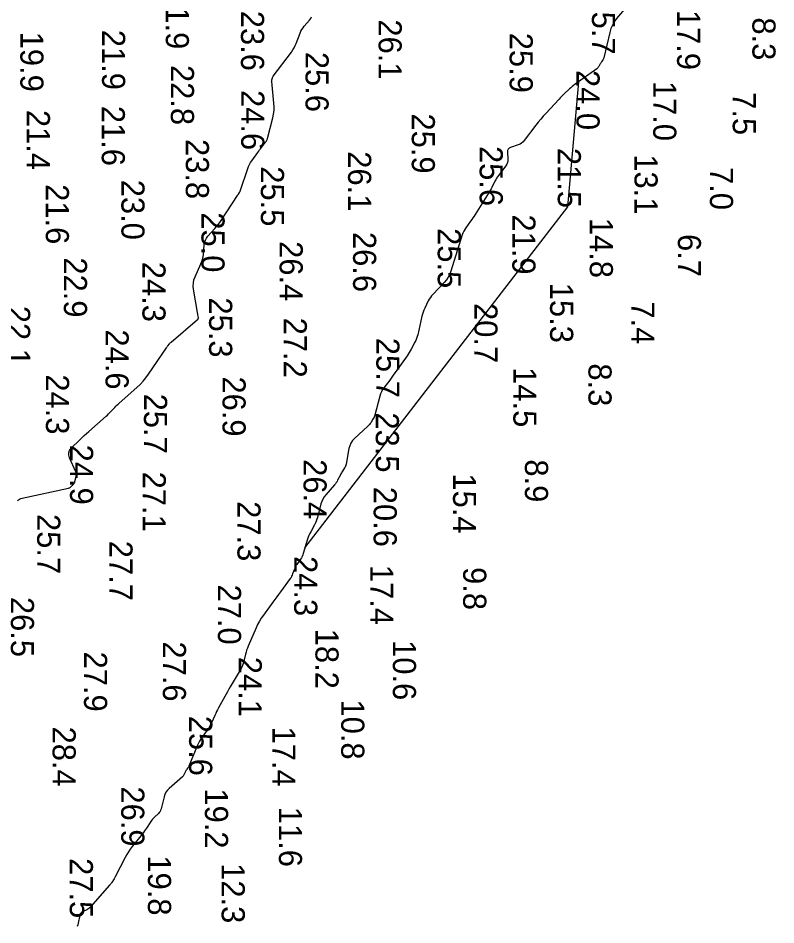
# Model space of a CAD drawing. Extents: x 1178573 to 1187098, y 693282 to 751751.
# Drawn here: x 1181936.7 to 1182346.5, y 721748.7 to 722239.3 of the extents above; entities that cross this region are included whole.
import ezdxf

# ---------------------------------------------------------------- set-up
doc = ezdxf.new("R2010")
doc.units = 0
for name, color, linetype in [('G-ANNO-PATT', 7, 'Continuous'), ('V-HYDS-MAJR', 7, 'Continuous'), ('V-HYDS-SOUN', 7, 'Continuous')]:
    doc.layers.add(name, color=color, linetype=linetype)

msp = doc.modelspace()

# ---------------------------------------------------------------- linework, layer by layer
at = {"layer": 'G-ANNO-PATT'}
for p, q in [((1182234, 722137.21), (1182239.89, 722204.89)), ((1182091.82, 721952.67), (1182234, 722137.21))]:
    msp.add_line(p, q, dxfattribs=at)
for points in [[(1181936.3, 721978.32), (1181936.88, 721978.75), (1181937.49, 721979.11), (1181938.14, 721979.38), (1181938.83, 721979.58), (1181964, 721985.05), (1181964.28, 721985.13), (1181964.55, 721985.24), (1181964.8, 721985.39), (1181965.03, 721985.57), (1181966.15, 721986.59), (1181966.25, 721986.69), (1181966.35, 721986.79), (1181966.44, 721986.89), (1181966.52, 721987), (1181966.86, 721987.44), (1181966.94, 721987.56), (1181967, 721987.68), (1181967.06, 721987.8), (1181967.1, 721987.93), (1181968.05, 721991.37), (1181968.16, 721991.98), (1181968.17, 721992.59), (1181968.07, 721993.19), (1181967.86, 721993.77), (1181964.47, 722001.36), (1181964.04, 722002.78), (1181964.05, 722004.12), (1181964.52, 722005.37), (1181965.43, 722006.54), (1181970.11, 722011.17), (1181971.27, 722012.31), (1181972.45, 722013.43), (1181973.65, 722014.54), (1181974.87, 722015.62), (1181984.36, 722024), (1181984.97, 722024.56), (1181985.57, 722025.12), (1181986.16, 722025.7), (1181986.74, 722026.3), (1181989.01, 722028.69), (1181989.58, 722029.29), (1181990.17, 722029.87), (1181990.77, 722030.44), (1181991.38, 722030.99), (1182000.93, 722039.48), (1182002.68, 722041.12), (1182004.31, 722042.87), (1182005.82, 722044.71), (1182007.23, 722046.65), (1182016.89, 722060.93), (1182017.09, 722061.21), (1182017.29, 722061.48), (1182017.49, 722061.75), (1182017.71, 722062.02), (1182018.57, 722063.08), (1182018.79, 722063.34), (1182019.02, 722063.59), (1182019.26, 722063.83), (1182019.52, 722064.06), (1182033.79, 722076.17), (1182034.02, 722076.41), (1182034.16, 722076.69), (1182034.22, 722076.99), (1182034.2, 722077.32), (1182033.96, 722078.7), (1182033.89, 722079.04), (1182033.83, 722079.39), (1182033.77, 722079.73), (1182033.71, 722080.08), (1182031.57, 722092.62), (1182031.4, 722094.33), (1182031.48, 722096), (1182031.81, 722097.65), (1182032.4, 722099.26), (1182035.59, 722106.43), (1182036.08, 722107.64), (1182036.45, 722108.88), (1182036.73, 722110.16), (1182036.89, 722111.45), (1182037.35, 722116.7), (1182037.56, 722117.97), (1182037.96, 722119.15), (1182038.56, 722120.26), (1182039.34, 722121.28), (1182043.14, 722125.48), (1182044.05, 722126.52), (1182044.91, 722127.6), (1182045.73, 722128.71), (1182046.51, 722129.85), (1182055.29, 722143.26), (1182055.42, 722143.47), (1182055.56, 722143.67), (1182055.69, 722143.87), (1182055.83, 722144.07), (1182056.38, 722144.87), (1182056.51, 722145.08), (1182056.63, 722145.29), (1182056.73, 722145.51), (1182056.82, 722145.73), (1182060.93, 722157.92), (1182061.35, 722159.04), (1182061.85, 722160.11), (1182062.43, 722161.15), (1182063.09, 722162.14), (1182066.32, 722166.64), (1182066.8, 722167.31), (1182067.29, 722167.98), (1182067.79, 722168.64), (1182068.29, 722169.3), (1182070.31, 722171.92), (1182070.77, 722172.59), (1182071.17, 722173.3), (1182071.49, 722174.05), (1182071.73, 722174.83), (1182074.46, 722185.27), (1182074.89, 722187.25), (1182075.13, 722189.25), (1182075.19, 722191.26), (1182075.07, 722193.29), (1182073.85, 722204.97), (1182073.83, 722205.23), (1182073.84, 722205.48), (1182073.88, 722205.74), (1182073.95, 722205.98), (1182074.26, 722206.97), (1182074.35, 722207.22), (1182074.45, 722207.45), (1182074.58, 722207.67), (1182074.73, 722207.88), (1182084.52, 722220.94), (1182085.29, 722222.05), (1182085.98, 722223.2), (1182086.59, 722224.4), (1182087.12, 722225.64), (1182089.24, 722231.2), (1182089.68, 722232.19), (1182090.19, 722233.14), (1182090.79, 722234.03), (1182091.48, 722234.88), (1182094.38, 722238.15), (1182095.01, 722239.01), (1182095.46, 722239.93)], [(1182239.89, 722204.89), (1182237.91, 722203.49), (1182237.12, 722202.9), (1182236.35, 722202.29), (1182235.6, 722201.65), (1182234.88, 722200.98), (1182232.03, 722198.26), (1182231.33, 722197.57), (1182230.63, 722196.87), (1182229.94, 722196.17), (1182229.27, 722195.45), (1182222.1, 722187.71), (1182220.7, 722186.16), (1182219.35, 722184.59), (1182218.03, 722182.98), (1182216.76, 722181.34), (1182210.49, 722173.07), (1182209.81, 722172.3), (1182209.04, 722171.65), (1182208.18, 722171.12), (1182207.23, 722170.73), (1182203.1, 722169.33), (1182202.3, 722168.94), (1182201.75, 722168.38), (1182201.44, 722167.66), (1182201.36, 722166.78), (1182201.55, 722162.93), (1182201.52, 722161.99), (1182201.33, 722161.1), (1182200.99, 722160.25), (1182200.49, 722159.46), (1182196.52, 722154.15), (1182195.98, 722153.4), (1182195.48, 722152.62), (1182195.01, 722151.83), (1182194.57, 722151.02), (1182192.89, 722147.72)], [(1182192.89, 722147.72), (1182192.47, 722146.9), (1182192.02, 722146.09), (1182191.56, 722145.3), (1182191.08, 722144.51), (1182183.9, 722133.05), (1182183.31, 722132.12), (1182182.7, 722131.21), (1182182.08, 722130.31), (1182181.44, 722129.41), (1182178.85, 722125.87), (1182178.24, 722124.97), (1182177.71, 722124.02), (1182177.26, 722123.03), (1182176.9, 722122), (1182170.78, 722102.41), (1182170.15, 722100.71), (1182169.33, 722099.12), (1182168.33, 722097.64), (1182167.16, 722096.26), (1182161.1, 722089.92), (1182160.36, 722089.08), (1182159.7, 722088.2), (1182159.1, 722087.28), (1182158.57, 722086.3), (1182156.61, 722082.29), (1182156.14, 722081.28), (1182155.74, 722080.24), (1182155.41, 722079.19), (1182155.13, 722078.11), (1182152.83, 722068), (1182152.56, 722066.96), (1182152.22, 722065.94), (1182151.81, 722064.95), (1182151.34, 722063.99), (1182149.31, 722060.17), (1182148.78, 722059.23), (1182148.23, 722058.31), (1182147.65, 722057.4), (1182147.04, 722056.51), (1182140.71, 722047.63), (1182139.96, 722046.58), (1182139.2, 722045.54), (1182138.44, 722044.5), (1182137.67, 722043.46), (1182134.57, 722039.34), (1182133.85, 722038.28), (1182133.24, 722037.17), (1182132.74, 722036.01), (1182132.35, 722034.79), (1182129.58, 722024.5), (1182129.4, 722023.94), (1182129.19, 722023.4), (1182128.94, 722022.87), (1182128.64, 722022.37), (1182127.38, 722020.38), (1182127.05, 722019.89), (1182126.69, 722019.43), (1182126.3, 722018.99), (1182125.89, 722018.58), (1182118.65, 722011.84), (1182117.57, 722010.68), (1182116.71, 722009.38), (1182116.08, 722007.97), (1182115.66, 722006.44), (1182114.04, 721997.91), (1182113.91, 721997.39), (1182113.74, 721996.89), (1182113.52, 721996.41), (1182113.25, 721995.95), (1182112.09, 721994.13), (1182111.8, 721993.67), (1182111.53, 721993.21), (1182111.27, 721992.73), (1182111.02, 721992.25), (1182109.53, 721989.25), (1182109.18, 721988.61), (1182108.79, 721987.98), (1182108.36, 721987.39), (1182107.89, 721986.82), (1182103.11, 721981.41), (1182102.22, 721980.28), (1182101.48, 721979.07), (1182100.89, 721977.79), (1182100.45, 721976.42), (1182098.54, 721969.18), (1182098.24, 721968.14), (1182097.88, 721967.14), (1182097.46, 721966.15), (1182096.97, 721965.19), (1182094.93, 721961.39), (1182094.44, 721960.43), (1182094, 721959.45), (1182093.62, 721958.45), (1182093.28, 721957.43), (1182091.82, 721952.67)]]:
    msp.add_lwpolyline(points, dxfattribs=at)
at = {"layer": 'V-HYDS-MAJR'}
for points in [[(1182266.72, 722246.45), (1182260.41, 722239.01), (1182259.14, 722237.32), (1182258.1, 722235.52), (1182257.27, 722233.61), (1182256.67, 722231.59), (1182253.44, 722217.8), (1182253.36, 722217.49), (1182253.24, 722217.2), (1182253.1, 722216.92), (1182252.92, 722216.65), (1182252.17, 722215.61), (1182251.99, 722215.35), (1182251.82, 722215.08), (1182251.66, 722214.81), (1182251.5, 722214.53), (1182250.72, 722213.03), (1182250.52, 722212.7), (1182250.29, 722212.41), (1182250.03, 722212.14), (1182249.73, 722211.9), (1182237.91, 722203.49), (1182237.12, 722202.9), (1182236.35, 722202.29), (1182235.6, 722201.65), (1182234.88, 722200.98), (1182232.03, 722198.26), (1182231.33, 722197.57), (1182230.63, 722196.87), (1182229.94, 722196.17), (1182229.27, 722195.45), (1182222.1, 722187.71), (1182220.7, 722186.16), (1182219.35, 722184.59), (1182218.03, 722182.98), (1182216.76, 722181.34), (1182210.49, 722173.07), (1182209.81, 722172.3), (1182209.04, 722171.65), (1182208.18, 722171.12), (1182207.23, 722170.73), (1182203.1, 722169.33), (1182202.3, 722168.94), (1182201.75, 722168.38), (1182201.44, 722167.66), (1182201.36, 722166.78), (1182201.55, 722162.93), (1182201.52, 722161.99), (1182201.33, 722161.1), (1182200.99, 722160.25), (1182200.49, 722159.46), (1182196.52, 722154.15), (1182195.98, 722153.4), (1182195.48, 722152.62), (1182195.01, 722151.83), (1182194.57, 722151.02), (1182192.89, 722147.72)], [(1181936.3, 721978.32), (1181936.88, 721978.75), (1181937.49, 721979.11), (1181938.14, 721979.38), (1181938.83, 721979.58), (1181964, 721985.05), (1181964.28, 721985.13), (1181964.55, 721985.24), (1181964.8, 721985.39), (1181965.03, 721985.57), (1181966.15, 721986.59), (1181966.25, 721986.69), (1181966.35, 721986.79), (1181966.44, 721986.89), (1181966.52, 721987), (1181966.86, 721987.44), (1181966.94, 721987.56), (1181967, 721987.68), (1181967.06, 721987.8), (1181967.1, 721987.93), (1181968.05, 721991.37), (1181968.16, 721991.98), (1181968.17, 721992.59), (1181968.07, 721993.19), (1181967.86, 721993.77), (1181964.47, 722001.36), (1181964.04, 722002.78), (1181964.05, 722004.12), (1181964.52, 722005.37), (1181965.43, 722006.54), (1181970.11, 722011.17), (1181971.27, 722012.31), (1181972.45, 722013.43), (1181973.65, 722014.54), (1181974.87, 722015.62), (1181984.36, 722024), (1181984.97, 722024.56), (1181985.57, 722025.12), (1181986.16, 722025.7), (1181986.74, 722026.3), (1181989.01, 722028.69), (1181989.58, 722029.29), (1181990.17, 722029.87), (1181990.77, 722030.44), (1181991.38, 722030.99), (1182000.93, 722039.48), (1182002.68, 722041.12), (1182004.31, 722042.87), (1182005.82, 722044.71), (1182007.23, 722046.65), (1182016.89, 722060.93), (1182017.09, 722061.21), (1182017.29, 722061.48), (1182017.49, 722061.75), (1182017.71, 722062.02), (1182018.57, 722063.08), (1182018.79, 722063.34), (1182019.02, 722063.59), (1182019.26, 722063.83), (1182019.52, 722064.06), (1182033.79, 722076.17), (1182034.02, 722076.41), (1182034.16, 722076.69), (1182034.22, 722076.99), (1182034.2, 722077.32), (1182033.96, 722078.7), (1182033.89, 722079.04), (1182033.83, 722079.39), (1182033.77, 722079.73), (1182033.71, 722080.08), (1182031.57, 722092.62), (1182031.4, 722094.33), (1182031.48, 722096), (1182031.81, 722097.65), (1182032.4, 722099.26), (1182035.59, 722106.43), (1182036.08, 722107.64), (1182036.45, 722108.88), (1182036.73, 722110.16), (1182036.89, 722111.45), (1182037.35, 722116.7), (1182037.56, 722117.97), (1182037.96, 722119.15), (1182038.56, 722120.26), (1182039.34, 722121.28), (1182043.14, 722125.48), (1182044.05, 722126.52), (1182044.91, 722127.6), (1182045.73, 722128.71), (1182046.51, 722129.85), (1182055.29, 722143.26), (1182055.42, 722143.47), (1182055.56, 722143.67), (1182055.69, 722143.87), (1182055.83, 722144.07), (1182056.38, 722144.87), (1182056.51, 722145.08), (1182056.63, 722145.29), (1182056.73, 722145.51), (1182056.82, 722145.73), (1182060.93, 722157.92), (1182061.35, 722159.04), (1182061.85, 722160.11), (1182062.43, 722161.15), (1182063.09, 722162.14), (1182066.32, 722166.64), (1182066.8, 722167.31), (1182067.29, 722167.98), (1182067.79, 722168.64), (1182068.29, 722169.3), (1182070.31, 722171.92), (1182070.77, 722172.59), (1182071.17, 722173.3), (1182071.49, 722174.05), (1182071.73, 722174.83), (1182074.46, 722185.27), (1182074.89, 722187.25), (1182075.13, 722189.25), (1182075.19, 722191.26), (1182075.07, 722193.29), (1182073.85, 722204.97), (1182073.83, 722205.23), (1182073.84, 722205.48), (1182073.88, 722205.74), (1182073.95, 722205.98), (1182074.26, 722206.97), (1182074.35, 722207.22), (1182074.45, 722207.45), (1182074.58, 722207.67), (1182074.73, 722207.88), (1182084.52, 722220.94), (1182085.29, 722222.05), (1182085.98, 722223.2), (1182086.59, 722224.4), (1182087.12, 722225.64), (1182089.24, 722231.2), (1182089.68, 722232.19), (1182090.19, 722233.14), (1182090.79, 722234.03), (1182091.48, 722234.88), (1182094.38, 722238.15), (1182095.01, 722239.01), (1182095.46, 722239.93)], [(1182192.89, 722147.72), (1182192.47, 722146.9), (1182192.02, 722146.09), (1182191.56, 722145.3), (1182191.08, 722144.51), (1182183.9, 722133.05), (1182183.31, 722132.12), (1182182.7, 722131.21), (1182182.08, 722130.31), (1182181.44, 722129.41), (1182178.85, 722125.87), (1182178.24, 722124.97), (1182177.71, 722124.02), (1182177.26, 722123.03), (1182176.9, 722122), (1182170.78, 722102.41), (1182170.15, 722100.71), (1182169.33, 722099.12), (1182168.33, 722097.64), (1182167.16, 722096.26), (1182161.1, 722089.92), (1182160.36, 722089.08), (1182159.7, 722088.2), (1182159.1, 722087.28), (1182158.57, 722086.3), (1182156.61, 722082.29), (1182156.14, 722081.28), (1182155.74, 722080.24), (1182155.41, 722079.19), (1182155.13, 722078.11), (1182152.83, 722068), (1182152.56, 722066.96), (1182152.22, 722065.94), (1182151.81, 722064.95), (1182151.34, 722063.99), (1182149.31, 722060.17), (1182148.78, 722059.23), (1182148.23, 722058.31), (1182147.65, 722057.4), (1182147.04, 722056.51), (1182140.71, 722047.63), (1182139.96, 722046.58), (1182139.2, 722045.54), (1182138.44, 722044.5), (1182137.67, 722043.46), (1182134.57, 722039.34), (1182133.85, 722038.28), (1182133.24, 722037.17), (1182132.74, 722036.01), (1182132.35, 722034.79), (1182129.58, 722024.5), (1182129.4, 722023.94), (1182129.19, 722023.4), (1182128.94, 722022.87), (1182128.64, 722022.37), (1182127.38, 722020.38), (1182127.05, 722019.89), (1182126.69, 722019.43), (1182126.3, 722018.99), (1182125.89, 722018.58), (1182118.65, 722011.84), (1182117.57, 722010.68), (1182116.71, 722009.38), (1182116.08, 722007.97), (1182115.66, 722006.44), (1182114.04, 721997.91), (1182113.91, 721997.39), (1182113.74, 721996.89), (1182113.52, 721996.41), (1182113.25, 721995.95), (1182112.09, 721994.13), (1182111.8, 721993.67), (1182111.53, 721993.21), (1182111.27, 721992.73), (1182111.02, 721992.25), (1182109.53, 721989.25), (1182109.18, 721988.61), (1182108.79, 721987.98), (1182108.36, 721987.39), (1182107.89, 721986.82), (1182103.11, 721981.41), (1182102.22, 721980.28), (1182101.48, 721979.07), (1182100.89, 721977.79), (1182100.45, 721976.42), (1182098.54, 721969.18), (1182098.24, 721968.14), (1182097.88, 721967.14), (1182097.46, 721966.15), (1182096.97, 721965.19), (1182094.93, 721961.39), (1182094.44, 721960.43), (1182094, 721959.45), (1182093.62, 721958.45), (1182093.28, 721957.43), (1182090.89, 721949.62), (1182090.62, 721948.83), (1182090.29, 721948.08), (1182089.9, 721947.35), (1182089.45, 721946.65), (1182087.37, 721943.67), (1182086.99, 721943.09), (1182086.65, 721942.48), (1182086.36, 721941.86), (1182086.11, 721941.21), (1182085.19, 721938.57), (1182084.94, 721937.92), (1182084.64, 721937.3), (1182084.29, 721936.7), (1182083.9, 721936.13), (1182078.59, 721928.92), (1182077.56, 721927.53), (1182076.54, 721926.13), (1182075.52, 721924.74), (1182074.5, 721923.35), (1182069.37, 721916.35), (1182068.22, 721914.69), (1182067.17, 721912.98), (1182066.23, 721911.21), (1182065.38, 721909.38), (1182061.12, 721899.46), (1182060.68, 721898.4), (1182060.29, 721897.32), (1182059.95, 721896.23), (1182059.65, 721895.12), (1182058.52, 721890.67), (1182058.2, 721889.57), (1182057.81, 721888.51), (1182057.34, 721887.47), (1182056.79, 721886.47), (1182051.46, 721877.52), (1182050.68, 721876.19), (1182049.92, 721874.87), (1182049.17, 721873.53), (1182048.43, 721872.19), (1182045.11, 721866.1), (1182044.58, 721865.11), (1182044.06, 721864.1), (1182043.56, 721863.09), (1182043.08, 721862.07), (1182041.2, 721857.96), (1182040.7, 721856.95), (1182040.16, 721855.97), (1182039.58, 721855.01), (1182038.94, 721854.07), (1182036.09, 721850.07), (1182035.42, 721849.08), (1182034.82, 721848.05), (1182034.27, 721847), (1182033.78, 721845.91), (1182029.07, 721834.54), (1182028.96, 721834.31), (1182028.84, 721834.08), (1182028.7, 721833.87), (1182028.55, 721833.67), (1182027.89, 721832.87), (1182027.74, 721832.67), (1182027.6, 721832.45), (1182027.47, 721832.23), (1182027.36, 721832), (1182026.56, 721830.19), (1182026.38, 721829.82), (1182026.16, 721829.48), (1182025.9, 721829.17), (1182025.6, 721828.88), (1182018.35, 721822.51), (1182017.41, 721821.54), (1182016.64, 721820.47), (1182016.04, 721819.29), (1182015.62, 721818.01), (1182014, 721811.41), (1182013.78, 721810.72), (1182013.46, 721810.07), (1182013.06, 721809.48), (1182012.56, 721808.94), (1182010.4, 721806.89), (1182009.87, 721806.36), (1182009.38, 721805.81), (1182008.92, 721805.23), (1182008.5, 721804.62), (1182006.18, 721801.08), (1182005.65, 721800.29), (1182005.1, 721799.52), (1182004.53, 721798.75), (1182003.95, 721798), (1181998.45, 721791.1), (1181997.37, 721789.68), (1181996.37, 721788.21), (1181995.44, 721786.69), (1181994.59, 721785.12), (1181989.27, 721774.7), (1181989.06, 721774.3), (1181988.83, 721773.91), (1181988.59, 721773.53), (1181988.34, 721773.15), (1181987.3, 721771.66), (1181987.03, 721771.29), (1181986.76, 721770.93), (1181986.47, 721770.58), (1181986.18, 721770.23), (1181975.89, 721758.39), (1181975.45, 721757.93), (1181974.96, 721757.52), (1181974.44, 721757.16), (1181973.88, 721756.86), (1181971.55, 721755.75), (1181971.02, 721755.42), (1181970.61, 721755.01), (1181970.31, 721754.51), (1181970.12, 721753.93), (1181969.21, 721749.63), (1181968.96, 721748.73), (1181968.61, 721747.89)]]:
    msp.add_lwpolyline(points, dxfattribs=at)

# ---------------------------------------------------------------- texts
at = {"layer": 'V-HYDS-SOUN'}
for s, p in [('21.9 ', (1182016.57, 722254.96)), ('25.7 ', (1182247.07, 722252.11)), ('23.6 ', (1182057.24, 722243.28)), ('17.9 ', (1182293.11, 722243.74)), ('26.1 ', (1182131.67, 722238.62)), ('8.3', (1182333.86, 722239.68)), ('21.9 ', (1181982.09, 722232.98)), ('19.9 ', (1181937.9, 722231.96)), ('25.9 ', (1182202.56, 722231.38)), ('25.6 ', (1182092.15, 722221.04)), ('22.8 ', (1182019.33, 722213.95)), ('24.0 ', (1182238.71, 722211.24)), ('17.0 ', (1182280.21, 722205.33)), ('24.6 ', (1182057.37, 722200.4)), ('7.5', (1182323.23, 722199.21)), ('21.4 ', (1181941.4, 722189.62)), ('21.6 ', (1181981.92, 722191.84)), ('25.9 ', (1182149.61, 722187.71)), ('23.8 ', (1182027.4, 722173.89)), ('25.6 ', (1182186.34, 722170.12)), ('21.5 ', (1182228.58, 722169.08)), ('26.1 ', (1182115.16, 722167.26)), ('13.1 ', (1182270.08, 722165.62)), ('25.5 ', (1182068.01, 722159.14)), ('7.0', (1182310.89, 722158.71)), ('21.6 ', (1181951.67, 722149.45)), ('23.0 ', (1181992.55, 722151.86)), ('25.0 ', (1182035.85, 722134.24)), ('21.9 ', (1182204.01, 722133.08)), ('14.8 ', (1182245.9, 722131.24)), ('25.5 ', (1182163.65, 722125.68)), ('26.6 ', (1182117.87, 722123.6)), ('6.7', (1182293.54, 722122.46)), ('26.4 ', (1182078.14, 722118.65)), ('22.9 ', (1181961.45, 722109.85)), ('24.3 ', (1182003.93, 722107.46)), ('15.3 ', (1182224.43, 722096.11)), ('25.3 ', (1182039.99, 722088.2)), ('7.4', (1182268.37, 722086.04)), ('22.1 ', (1181930.71, 722083.66)), ('20.7 ', (1182183.49, 722085.15)), ('27.2 ', (1182080.36, 722077.24)), ('24.6 ', (1181983.98, 722070.88)), ('25.7 ', (1182130.44, 722066.35)), ('8.3', (1182245.18, 722052.48)), ('24.3 ', (1181951.76, 722046.56)), ('14.5 ', (1182204.56, 722050.45)), ('26.9 ', (1182047.25, 722045.45)), ('25.7 ', (1182004.78, 722036.13)), ('23.5 ', (1182130.15, 722025.97)), ('24.9 ', (1181964.77, 722008.54)), ('26.4 ', (1182091.07, 722000.68)), ('8.9', (1182210.83, 722000.55)), ('27.1 ', (1182004.07, 721993.93)), ('15.4 ', (1182171.94, 721992.97)), ('20.6 ', (1182129, 721985.74)), ('27.3 ', (1182055.31, 721977.93)), ('25.7 ', (1181947.01, 721971.01)), ('27.7 ', (1181986.08, 721956.54)), ('24.3 ', (1182086.02, 721948.27)), ('17.4 ', (1182127.13, 721943.49)), ('9.8', (1182177.43, 721942.28)), ('27.0 ', (1182044.78, 721932.83)), ('26.5 ', (1181932.78, 721926.14)), ('18.2 ', (1182097.52, 721908.93)), ('27.6 ', (1182014.99, 721902.08)), ('10.6 ', (1182139.4, 721902.77)), ('27.9 ', (1181972.35, 721896.57)), ('24.1 ', (1182055.98, 721893.74)), ('10.8 ', (1182111.45, 721870.65)), ('25.6 ', (1182029.19, 721861.85)), ('28.4 ', (1181955.34, 721855.99)), ('17.4 ', (1182074.21, 721856.02)), ('26.9 ', (1181992.46, 721823.63)), ('19.2 ', (1182037.75, 721822.55)), ('11.6 ', (1182077.75, 721812.58)), ('27.5 ', (1181964.64, 721784.83)), ('19.8 ', (1182006.93, 721786.3)), ('12.3 ', (1182046.78, 721782.1))]:
    msp.add_text(s, height=12.5, rotation=270, dxfattribs=at).set_placement(p)

doc.saveas('drawing.dxf')
